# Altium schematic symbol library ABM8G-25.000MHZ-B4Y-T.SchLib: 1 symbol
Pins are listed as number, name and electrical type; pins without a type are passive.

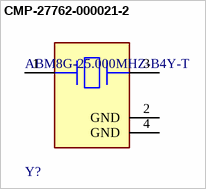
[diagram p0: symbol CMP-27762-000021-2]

## CMP-27762-000021-2
designator Y?, comment ABM8G-25.000MHZ-B4Y-T
Crystal 25MHz ±30ppm (Tol) ±30ppm (Stability) 10pF FUND 60Ω 4-Pin SMD T/R; ESR (Equivalent Series Resistance): 60R
footprint FP-ABM8G-MFG
pins: 1, 2 GND (power), 3, 4 GND (power)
